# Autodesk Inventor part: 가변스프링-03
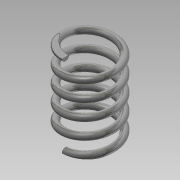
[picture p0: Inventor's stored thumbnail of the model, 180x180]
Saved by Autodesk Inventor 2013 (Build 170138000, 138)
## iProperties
Created: 2014-12
Part Number: 가변스프링-03
Material: 강철, 탄소
Document SubType Name: Modeling
Designer: hanacad19
Density: 7.87 g/cm^3
Mass: 18.8932 g
Surface Area: 32.5247 cm^2
Volume: 2.40066 cm^3
Author: hanacad19
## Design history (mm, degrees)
sketch "스케치1"
  geometry: L1 (0, 0)-(-11, 0); L2 (-11, 0)-(-11, 36.411); L3 (-11, 36.411)-(0, 36.411); L4 (0, 36.411)-(0, 0); C1 r 1.5 at (-11, 0)
  constraints: 8 end point, 2 parallel, 1 centre point, 1 horizontal, 1 perpendicular
  dimensions: "d0" = 3 diameter of C1; "d2" = 22 diameter of L2 L4; "d3" = 36.4112 distance between parallel lines of L1 L3 (derived)
feature "코일1" sketch "스케치1" pitch "d4" = 10; turns "d6" = 5; dims "d5" = 36.4112 (= d3), "d7" = 0, angle "d8" = 90 deg, angle "d9" = 90 deg, "d10" = 0, "d11" = 0
sketch "스케치2"
  geometry: L1 (0, -12.5)-(0, -9.5) reference; 1 further point
  constraints: 1 vertical alignment
extrude "돌출1" cut sketch "스케치2" distance "d12" = 10; taper "d13" = 0 deg
node "작업 평면1"
sketch "스케치3"
  geometry: L1 (0, -9.5)-(0, -12.5) reference; 1 further point
  constraints: 1 vertical alignment
extrude "돌출2" cut sketch "스케치3" distance "d14" = 10; taper "d15" = 0 deg
node "솔리드1"
node "절단 모서리 투영1"
node "절단 모서리 투영2"
